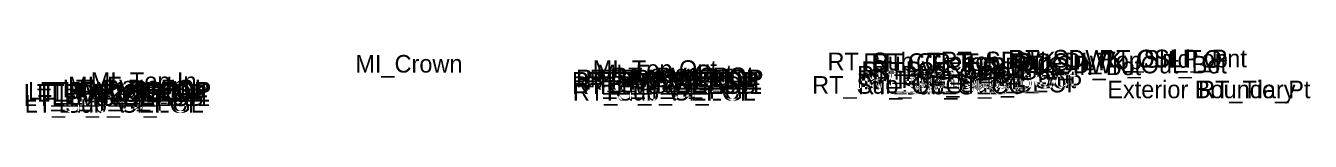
# Model space of a CAD drawing. Extents: x -26 to 6300, y -10 to 9528.
# Drawn here: x 3134.6 to 3207.6, y 4000.9 to 4004.8 of the extents above; entities that cross this region are included whole.
import ezdxf

# ---------------------------------------------------------------- set-up
doc = ezdxf.new("R2010")
doc.units = 0
doc.layers.add('Default', color=7, linetype='Continuous')

msp = doc.modelspace()

# ---------------------------------------------------------------- texts
at = {"layer": 'Default'}
for s, p in [('RT_Sub_Trench_Out_DLT', (3180.188, 4003.592)), ('RT_CG_Top_Face', (3182.221, 4003.552)), ('RT_CG_Top_BOC', (3182.69, 4003.552)), ('RT_SDWK_In_Top', (3186.617, 4003.642)), ('RT_SDWK_Out_Top', (3190.459, 4003.742)), ('RT_Shld_O', (3195.629, 4003.732)), ('CSLP_Pnt', (3197.782, 4003.757)), ('MI_Crown', (3153.346, 4003.456)), ('MI_Top Out', (3166.841, 4003.158)), ('MI_Face Out', (3167.053, 4002.908)), ('RT_PV2_OEOT', (3181.869, 4002.837)), ('RT_PV1_OEOT', (3182.108, 4003.087)), ('RT_CG_Top_Gut', (3182.748, 4003.052)), ('RT_SDWK_In_Bot', (3186.866, 4003.309)), ('RT_SDWK_Out_Bot', (3190.708, 4003.409)), ('MI_Face In', (3137.015, 4002.215)), ('MI_Top In', (3138.303, 4002.465)), ('RT_PV2_OEEOP', (3165.663, 4002.492)), ('RT_PV3_OEEOP', (3165.663, 4002.242)), ('RT_PV1_OEEOP', (3165.903, 4002.617)), ('RT_PV2_IEEOP', (3166.424, 4002.492)), ('RT_PV1_IEEOP', (3166.663, 4002.617)), ('RT_PV2_PGL1', (3167.263, 4002.492)), ('RT_PV3_PGL1', (3167.263, 4002.242)), ('RT_PV2_PGL', (3167.642, 4002.492)), ('RT_PV1_PGL', (3167.881, 4002.742)), ('MI_Bot Out', (3168.244, 4002.742)), ('RT_Sub_OEOT_CG', (3179.314, 4002.254)), ('RT_PV3_OEOT', (3181.869, 4002.587)), ('RT_Sub_OEOT', (3181.916, 4002.212)), ('RT_CG_Bot_IE', (3182.217, 4002.504)), ('RT_CG1_Shelf_Out', (3182.356, 4002.571)), ('RT_CG_Bot_BOC', (3182.966, 4002.56)), ('RT_Sub_OEOP', (3185.152, 4002.326)), ('LT_PV2_OEEOP', (3134.499, 4001.798)), ('LT_PV3_OEEOP', (3134.499, 4001.548)), ('LT_PV1_OEEOP', (3134.739, 4001.923)), ('LT_PV2_IEEOP', (3135.26, 4001.798)), ('LT_PV1_IEEOP', (3135.499, 4001.923)), ('LT_PV2_PGL1', (3136.098, 4001.798)), ('LT_PV3_PGL1', (3136.098, 4001.548)), ('LT_PV2_PGL', (3136.478, 4001.798)), ('LT_PV1_PGL', (3136.717, 4002.048)), ('MI_Bot In', (3138.185, 4002.048)), ('RT_Sub_OEEOP', (3165.71, 4001.867)), ('RT_PV4_PGL', (3167.642, 4001.867)), ('Exterior Boundary', (3196.088, 4001.998)), ('RT_Tie_Pt', (3201.25, 4001.998)), ('LT_Sub_OEEOP', (3134.546, 4001.173)), ('LT_PV4_PGL', (3136.478, 4001.173))]:
    msp.add_text(s, height=1, dxfattribs=at).set_placement(p)

doc.saveas('drawing.dxf')
